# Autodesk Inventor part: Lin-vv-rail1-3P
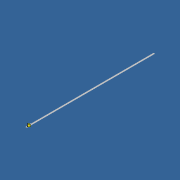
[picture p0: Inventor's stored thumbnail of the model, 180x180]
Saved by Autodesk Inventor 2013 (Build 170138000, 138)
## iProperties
Created: 2012-05
Part Number: Lin-vv-rail1-3P
Document SubType Name: Modeling
Designer: ssc
Density: 7.9 g/cm^3
Material: Stainless Steel, 304
Mass: 59780.8 g
Surface Area: 17821.9 cm^2
Volume: 7567.19 cm^3
Author: ssc
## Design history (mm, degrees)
sketch "Sketch1" dims "d0" = 946.15, "d9" = 350.012
  geometry: L1 (-171.45, 398.323)-(171.45, 398.323); L2 (171.45, 398.323)-(171.45, 416.103); L3 (171.45, 416.103)-(-171.45, 416.103); L4 (-171.45, 416.103)-(-171.45, 398.323); L5 (0, 0)-(0, 522.288); L6 (-227.13, 378.663)-(52.27, 378.663); L7 (-166.688, 93.663)-(-166.688, -53.314); L8 (-172.49, 393.268)-(-172.49, 385.013); L9 (-172.49, 385.013)-(-210.439, 385.013); L10 (-248.69, 385.013)-(-248.69, 394.538); L11 (-200.695, 394.538)-(-197.89, 394.538); L12 (-215.861, 395.808)-(-248.69, 395.808); L13 (-251.421, 400.734)-(-216.971, 419.829); L14 (-215.861, 417.826)-(-215.861, 395.808); L15 (-216.971, 419.829)-(-215.861, 417.826); L16 (-251.421, 400.734)-(-248.69, 395.808); L17 (-184.633, 421.949)-(-195.631, 421.949); L18 (-195.631, 421.949)-(-195.631, 401.959); L19 (-195.631, 401.959)-(-184.633, 401.959); L20 (-184.633, 401.959)-(-184.633, 421.949); L21 (-248.69, 385.013)-(-210.59, 385.013); L22 (-210.59, 385.013)-(-210.439, 385.013); L23 (-248.69, 394.538)-(-218.528, 394.538); L24 (-205.828, 397.713)-(-205.828, 413.588); L25 (-205.828, 413.588)-(-215.353, 413.588); L26 (-215.353, 413.588)-(-215.353, 397.713); L27 (-212.725, 413.588)-(-215.353, 413.588); L28 (-248.69, 394.538)-(-218.528, 394.538); L29 (-202.653, 394.538)-(-197.89, 394.538); L30 (-172.49, 393.268)-(-197.89, 393.268); L31 (-197.89, 393.268)-(-197.89, 394.538); A1 r 3.175 centre (-202.653, 397.713) between (-205.828, 397.713) and (-202.653, 394.538); A2 r 3.175 centre (-218.528, 397.713) between (-218.528, 394.538) and (-215.353, 397.713); 5 further points
  constraints: 62 end point, 11 parallel, 10 perpendicular, 10 point on line, 7 horizontal, 4 point on circle, 4 tangent, 2 centre point, 1 coincident, 1 collinear, 1 equal radius, 7 other
  dimensions: "d1" = 398.3228 distance from line of L5.start L1; "d2" = 17.78 distance of L1.end L2.end; "d3" = 342.9 distance of L2.end L3.end; "d4" = 171.45 distance between parallel lines of L2 L5; "d5" = 19.6596 distance between parallel lines of L6 L1; "d23" = 61 deg angle of L14 L13; "d24" = 1.27 distance of L13.end point (-215.861, 420.445); "d25" = 90 deg angle of L13 L15; "d26" = 10.16 distance of L13.start point (-260.307, 395.808); "d27" = 90 deg angle of L13 L16 (= d25); "d29" = 35.56 distance from line of L14 L13.start; "d30" = 6.35 distance between parallel lines of L6 L9; "d55" = 19.9898 distance of L17.end L18.end; "d56" = 10.9982 distance of L17.start L17.end; "d58" = 184.6326 distance between parallel lines of L5 L20; "d63" = 9.525 distance of L10.start L10.end; "d64" = 38.1 distance of L10.start L21.end; "d69" = 76.2 distance between parallel lines of L8 L10; "d70" = 9.525 distance of L24.end L25.end; "d71" = 19.05 distance of point (-205.828, 394.538) L24.end; "d78" = 25.4 distance of L8.start L30.end; "d79" = 1.27 distance between parallel lines of L30 L29; "d80" = 3.175 radius of A1; "d87" = 33.3375 distance between parallel lines of L10 L26; "d88" = 9.525 distance between parallel lines of L9 L29
extrude "Extrusion1" new body sketch "Sketch1" distance "d32" = 8686.8; taper "d33" = 0 deg
chamfer "Chamfer1" distance "d34" = 1.27; stored, may be unused: second distance "d35" = 3.175, angle "d36" = 45 deg
hole "Hole1" diameter "d42" = 10.3124; stored, may be unused: countersink angle "d46" = 82 deg, drill point angle "d48" = 118 deg; dims "d40" = 25.4, "d41" = 17.4625, "d43" = 12.7, "d44" = 15.875, "d45" = 9.779, "d47" = 19.05
hole "Hole2" diameter "d94" = 7.7978; stored, may be unused: countersink angle "d98" = 82 deg, drill point angle "d100" = 118 deg; dims "d92" = 17.4625, "d93" = 152.4, "d95" = 12.7, "d96" = 9.525, "d97" = 6.35, "d99" = 19.05
body "Solid1"
pattern_linear "Rectangular Pattern1" dims "d51" = 254
pattern_linear "Rectangular Pattern2" dims "d103" = 254
other parameters: "d31" = 1.27
